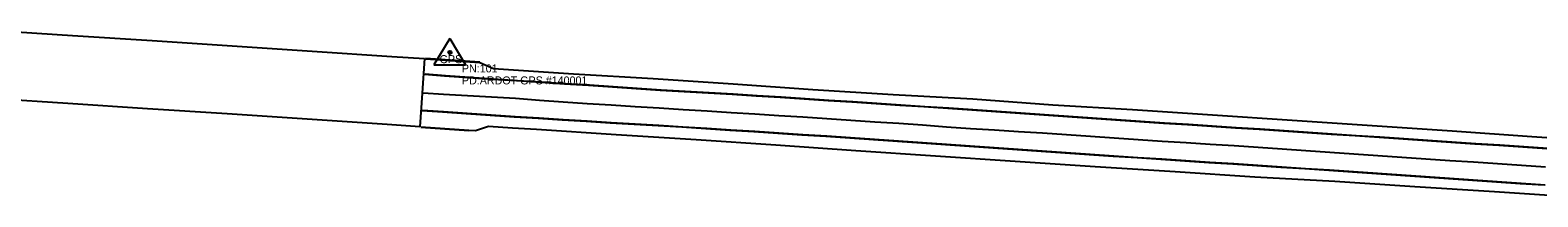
# Model space of a CAD drawing. Extents: x 878399 to 889864, y 1564003 to 1567413.
# Drawn here: x 880549 to 881491, y 1567175 to 1567279 of the extents above; entities that cross this region are included whole.
import ezdxf

# ---------------------------------------------------------------- set-up
doc = ezdxf.new("R2010")
doc.units = 0
for name, color, linetype in [('S_BRIDGE', 7, 'Continuous'), ('S_CURB', 7, 'Continuous'), ('S_EDGE_PAVEMENT', 7, 'Continuous'), ('S_PAVEMENT_CROWN', 7, 'Continuous'), ('S_PRIMARY_CTL', 7, 'Continuous'), ('S_PRIMARY_CTL_ANNOT', 7, 'Continuous'), ('S_SHOULDER', 7, 'Continuous')]:
    doc.layers.add(name, color=color, linetype=linetype)

msp = doc.modelspace()

# ---------------------------------------------------------------- linework, layer by layer
at = {"layer": 'S_BRIDGE'}
for p, q in [((880525.79, 1567279.11), (880575.69, 1567275.87)), ((880575.69, 1567275.87), (880625.58, 1567272.58)), ((880625.58, 1567272.58), (880675.59, 1567269.33)), ((880675.59, 1567269.33), (880725.47, 1567265.91)), ((880725.47, 1567265.91), (880775.38, 1567262.69)), ((880775.38, 1567262.69), (880795.8, 1567261.39)), ((880795.8, 1567261.39), (880794.31, 1567239.72)), ((880572.83, 1567233.26), (880522.94, 1567236.56)), ((880622.73, 1567230.02), (880572.83, 1567233.26)), ((880794.31, 1567239.72), (880792.86, 1567218.77)), ((880672.5, 1567226.78), (880622.73, 1567230.02)), ((880722.39, 1567223.47), (880672.5, 1567226.78)), ((880772.29, 1567220.15), (880722.39, 1567223.47)), ((880792.86, 1567218.77), (880772.29, 1567220.15))]:
    msp.add_line(p, q, dxfattribs=at)
at = {"layer": 'S_CURB'}
for points in [[(880796.32, 1567261.58), (880830.38, 1567259.4)], [(880793.34, 1567218.51), (880808.48, 1567217.44), (880823.45, 1567216.51)]]:
    msp.add_lwpolyline(points, dxfattribs=at)
at = {"layer": 'S_EDGE_PAVEMENT'}
for points in [[(880795.61, 1567251.58), (880808.3, 1567250.64), (880823.26, 1567249.53), (880838.23, 1567248.51), (880853.2, 1567247.55), (880868.17, 1567246.59), (880868.17, 1567246.59), (880868.17, 1567246.59), (880883.14, 1567245.63), (880898.11, 1567244.65), (880913.08, 1567243.66), (880928.05, 1567242.67), (880943.02, 1567241.71), (880958, 1567240.82), (880958, 1567240.82), (880972.97, 1567239.94), (880972.97, 1567239.94), (880987.95, 1567239.05), (881002.92, 1567238.1), (881017.89, 1567237.14), (881032.86, 1567236.19), (881047.83, 1567235.23), (881062.8, 1567234.26), (881062.8, 1567234.26), (881062.8, 1567234.26), (881077.83, 1567233.28), (881092.8, 1567232.3), (881107.77, 1567231.3), (881122.73, 1567230.31), (881137.7, 1567229.31), (881152.67, 1567228.25), (881167.63, 1567227.19), (881182.59, 1567226.13), (881197.56, 1567225.09), (881212.52, 1567224.06), (881227.49, 1567223.03), (881242.45, 1567222.02), (881257.42, 1567221.05), (881257.42, 1567221.05), (881272.39, 1567220.08), (881272.39, 1567220.08), (881272.39, 1567220.08), (881287.36, 1567219.11), (881302.33, 1567218.14), (881317.3, 1567217.17), (881332.27, 1567216.2), (881347.24, 1567215.21), (881362.19, 1567214.19), (881377.16, 1567213.18), (881392.12, 1567212.17), (881407.09, 1567211.16), (881422.06, 1567210.15), (881437.03, 1567209.15), (881451.99, 1567208.15), (881466.96, 1567207.15), (881481.93, 1567206.16), (881481.93, 1567206.16), (881481.93, 1567206.16), (881496.9, 1567205.15)], [(880796.22, 1567251.77), (880808.92, 1567250.83), (880823.88, 1567249.72), (880838.85, 1567248.7), (880853.82, 1567247.74), (880868.79, 1567246.78), (880868.79, 1567246.78), (880868.79, 1567246.78), (880883.76, 1567245.83), (880898.73, 1567244.85), (880913.69, 1567243.85), (880928.66, 1567242.86), (880943.63, 1567241.9), (880958.61, 1567241.01), (880958.61, 1567241.01), (880973.58, 1567240.13), (880973.58, 1567240.13), (880988.56, 1567239.24), (881003.53, 1567238.29), (881018.5, 1567237.34), (881033.47, 1567236.38), (881048.44, 1567235.42), (881063.4, 1567234.45), (881063.4, 1567234.45), (881063.4, 1567234.45), (881078.43, 1567233.47), (881093.4, 1567232.49), (881108.37, 1567231.5), (881123.34, 1567230.5), (881138.3, 1567229.5), (881153.27, 1567228.44), (881168.23, 1567227.38), (881183.19, 1567226.32), (881198.16, 1567225.28), (881213.12, 1567224.25), (881228.09, 1567223.22), (881243.05, 1567222.21), (881258.01, 1567221.24), (881258.01, 1567221.24), (881272.98, 1567220.27), (881272.98, 1567220.27), (881272.98, 1567220.27), (881287.95, 1567219.3), (881302.92, 1567218.34), (881317.89, 1567217.37), (881332.86, 1567216.4), (881347.83, 1567215.4), (881362.78, 1567214.38), (881377.75, 1567213.37), (881392.71, 1567212.36), (881407.68, 1567211.35), (881422.65, 1567210.35), (881437.61, 1567209.34), (881452.58, 1567208.34), (881467.55, 1567207.35), (881482.52, 1567206.35), (881482.52, 1567206.35), (881482.52, 1567206.35), (881497.48, 1567205.34)], [(880794.08, 1567228.86), (880806.87, 1567228.07), (880806.87, 1567228.07), (880821.84, 1567227.05), (880836.81, 1567226.05), (880836.81, 1567226.05), (880851.77, 1567225.01), (880866.74, 1567224.04), (880881.72, 1567223.12), (880896.69, 1567222.2), (880911.66, 1567221.28), (880911.66, 1567221.28), (880911.66, 1567221.28), (880926.64, 1567220.39), (880941.61, 1567219.5), (880956.58, 1567218.61), (880971.55, 1567217.68), (880971.55, 1567217.68), (880971.55, 1567217.68), (880986.52, 1567216.71), (881001.49, 1567215.73), (881016.46, 1567214.76), (881031.43, 1567213.78), (881031.43, 1567213.78), (881046.4, 1567212.8), (881061.37, 1567211.83), (881061.37, 1567211.83), (881076.26, 1567210.82), (881076.26, 1567210.82), (881076.26, 1567210.82), (881091.22, 1567209.79), (881106.19, 1567208.77), (881106.19, 1567208.77), (881106.19, 1567208.77), (881121.15, 1567207.73), (881136.12, 1567206.68), (881151.08, 1567205.64), (881166.05, 1567204.59), (881181.01, 1567203.53), (881195.98, 1567202.48), (881210.94, 1567201.42), (881225.91, 1567200.42), (881240.89, 1567199.43), (881255.85, 1567198.44), (881270.82, 1567197.46), (881285.79, 1567196.51), (881300.77, 1567195.55), (881315.74, 1567194.59), (881330.7, 1567193.58), (881345.67, 1567192.56), (881360.65, 1567191.55), (881375.62, 1567190.52), (881390.58, 1567189.49), (881405.55, 1567188.47), (881420.51, 1567187.44), (881435.48, 1567186.42), (881450.45, 1567185.4), (881465.41, 1567184.37), (881480.38, 1567183.37), (881495.35, 1567182.36)], [(880794.7, 1567229.06), (880807.49, 1567228.26), (880807.49, 1567228.26), (880822.46, 1567227.24), (880837.42, 1567226.24), (880837.42, 1567226.24), (880852.39, 1567225.21), (880867.36, 1567224.23), (880882.33, 1567223.32), (880897.3, 1567222.4), (880912.27, 1567221.48), (880912.27, 1567221.48), (880912.27, 1567221.48), (880927.25, 1567220.58), (880942.22, 1567219.69), (880957.19, 1567218.8), (880972.16, 1567217.88), (880972.16, 1567217.88), (880972.16, 1567217.88), (880987.13, 1567216.9), (881002.1, 1567215.92), (881017.07, 1567214.95), (881032.04, 1567213.97), (881032.04, 1567213.97), (881047.01, 1567213), (881061.98, 1567212.02), (881061.98, 1567212.02), (881076.86, 1567211.01), (881076.86, 1567211.01), (881076.86, 1567211.01), (881091.83, 1567209.99), (881106.79, 1567208.96), (881106.79, 1567208.96), (881106.79, 1567208.96), (881121.76, 1567207.92), (881136.72, 1567206.88), (881151.68, 1567205.83), (881166.65, 1567204.78), (881181.61, 1567203.73), (881196.57, 1567202.67), (881211.54, 1567201.62), (881226.5, 1567200.61), (881241.48, 1567199.62), (881256.45, 1567198.63), (881271.42, 1567197.66), (881286.39, 1567196.7), (881301.36, 1567195.74), (881316.33, 1567194.78), (881331.29, 1567193.77), (881346.26, 1567192.76), (881361.24, 1567191.74), (881376.21, 1567190.72), (881391.17, 1567189.69), (881406.14, 1567188.66), (881421.1, 1567187.63), (881436.07, 1567186.61), (881451.03, 1567185.59), (881466, 1567184.57), (881480.96, 1567183.56), (881495.93, 1567182.55)]]:
    msp.add_lwpolyline(points, dxfattribs=at)
at = {"layer": 'S_PAVEMENT_CROWN'}
msp.add_lwpolyline([(880794.9, 1567239.93), (880807.58, 1567239.21), (880822.55, 1567238.35), (880837.53, 1567237.49), (880837.53, 1567237.49), (880837.53, 1567237.49), (880852.5, 1567236.52), (880867.46, 1567235.44), (880867.46, 1567235.44), (880882.43, 1567234.36), (880882.43, 1567234.36), (880882.43, 1567234.36), (880897.39, 1567233.3), (880897.39, 1567233.3), (880912.36, 1567232.38), (880927.34, 1567231.46), (880927.34, 1567231.46), (880942.31, 1567230.54), (880942.31, 1567230.54), (880957.28, 1567229.59), (880957.28, 1567229.59), (880972.25, 1567228.65), (880987.22, 1567227.7), (880987.22, 1567227.7), (881002.19, 1567226.75), (881017.17, 1567225.8), (881017.17, 1567225.8), (881017.17, 1567225.8), (881032.14, 1567224.85), (881032.14, 1567224.85), (881047.11, 1567223.89), (881047.11, 1567223.89), (881062.07, 1567222.89), (881062.07, 1567222.89), (881062.07, 1567222.89), (881077.03, 1567221.89), (881092, 1567220.89), (881106.96, 1567219.85), (881106.96, 1567219.85), (881121.93, 1567218.79), (881121.93, 1567218.79), (881121.93, 1567218.79), (881136.89, 1567217.74), (881151.86, 1567216.75), (881151.86, 1567216.75), (881151.86, 1567216.75), (881166.83, 1567215.81), (881181.8, 1567214.87), (881181.8, 1567214.87), (881181.8, 1567214.87), (881196.78, 1567213.91), (881196.78, 1567213.91), (881211.74, 1567212.87), (881226.7, 1567211.82), (881241.67, 1567210.77), (881241.67, 1567210.77), (881241.67, 1567210.77), (881256.64, 1567209.82), (881271.61, 1567208.89), (881271.61, 1567208.89), (881286.59, 1567207.96), (881286.59, 1567207.96), (881286.59, 1567207.96), (881301.56, 1567206.97), (881316.52, 1567205.93), (881331.49, 1567204.9), (881346.45, 1567203.87), (881346.45, 1567203.87), (881346.45, 1567203.87), (881361.42, 1567202.84), (881376.39, 1567201.82), (881391.35, 1567200.8), (881406.32, 1567199.78), (881421.28, 1567198.76), (881436.25, 1567197.74), (881451.22, 1567196.73), (881451.22, 1567196.73), (881451.22, 1567196.73), (881466.19, 1567195.72), (881466.19, 1567195.72), (881481.15, 1567194.7), (881496.12, 1567193.7)], dxfattribs=at)
at = {"layer": 'S_PRIMARY_CTL'}
for p, q in [((880811.59, 1567273.9), (880801.56, 1567257.39)), ((880811.59, 1567273.9), (880821.41, 1567257.39)), ((880801.56, 1567257.39), (880821.41, 1567257.39))]:
    msp.add_line(p, q, dxfattribs=at)
for radius in [1.04, 0.609, 0.344]:
    msp.add_circle((880811.59, 1567265.2), radius, dxfattribs=at)
at = {"layer": 'S_SHOULDER'}
for points in [[(880796.3, 1567261.28), (880830.35, 1567258.88), (880838.86, 1567255.11), (880888.75, 1567251.8), (880938.68, 1567248.99), (880988.57, 1567245.59), (881038.44, 1567242.05), (881088.44, 1567238.83), (881138.38, 1567236.11), (881188.26, 1567232.54), (881238.15, 1567229.44), (881288.04, 1567226.13), (881337.94, 1567222.9), (881387.81, 1567219.48), (881437.71, 1567216.29), (881487.59, 1567212.73), (881537.45, 1567209.26)], [(880793.36, 1567218.8), (880808.5, 1567217.66), (880823.46, 1567216.66), (880827.6, 1567216.47), (880835.67, 1567219.02), (880850.65, 1567218.16), (880865.62, 1567217.19), (880915.52, 1567214.01), (880965.42, 1567210.84), (881015.31, 1567207.41), (881065.19, 1567203.96), (881114.96, 1567200.65), (881164.84, 1567197.27), (881214.74, 1567193.96), (881264.66, 1567190.79), (881314.56, 1567187.52), (881364.5, 1567184.65), (881414.41, 1567181.49), (881464.3, 1567178.2), (881514.23, 1567174.95)]]:
    msp.add_lwpolyline(points, dxfattribs=at)

# ---------------------------------------------------------------- texts
at = {"layer": 'S_PRIMARY_CTL'}
msp.add_text('GPS', height=5, rotation=360, dxfattribs=at).set_placement((880805.15, 1567258.49))
at = {"layer": 'S_PRIMARY_CTL_ANNOT'}
for s, p in [('PN:101', (880819.09, 1567252.7)), ('PD:ARDOT GPS #140001', (880819.09, 1567245.2))]:
    msp.add_text(s, height=5, dxfattribs=at).set_placement(p)

doc.saveas('drawing.dxf')
